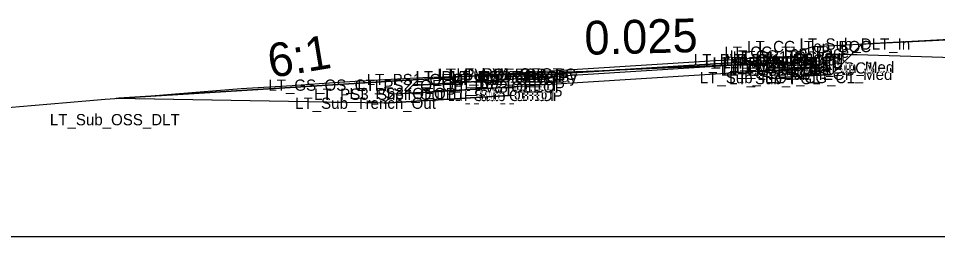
# Model space of a CAD drawing. Extents: x -26 to 2349090, y -10 to 844481.
# Drawn here: x 1098.25 to 1139.03, y 16500 to 16509.69 of the extents above; entities that cross this region are included whole.
import ezdxf

# ---------------------------------------------------------------- set-up
doc = ezdxf.new("R2010")
doc.units = 0
for name, color, linetype in [('Exist CMT Pavement', 7, 'Continuous'), ('Exist Cross Section Cell', 7, 'Continuous'), ('Exist XS Ground Line', 7, 'Continuous'), ('Prop CMT Conc Surface', 7, 'Continuous'), ('Prop CMT Concrete Structures', 7, 'Continuous'), ('Prop CMT Pvmt Course 1', 7, 'Continuous'), ('Prop CMT Pvmt Course 1 CG', 7, 'Continuous'), ('Prop CMT Pvmt Course 1 Wedge', 7, 'Continuous'), ('Prop CMT Pvmt Course 2', 7, 'Continuous'), ('Prop CMT Pvmt Course 2 Wedge', 7, 'Continuous'), ('Prop CMT Pvmt Course 3', 7, 'Continuous'), ('Prop CMT Pvmt Surface', 7, 'Continuous'), ('Prop CMT Pvmt Surface Shoulder', 7, 'Continuous'), ('Prop CMT Pvmt Wedge Surface 1', 7, 'Continuous'), ('Prop CMT Pvmt Wedge Surface 2', 7, 'Continuous'), ('Prop CMT Pvmt Wedge Surface 3', 7, 'Continuous'), ('Prop CMT Shld Paved Course 1', 7, 'Continuous'), ('Prop CMT Shld Paved Course 2', 7, 'Continuous'), ('Prop CMT Shld Paved Course 3', 7, 'Continuous'), ('Prop CMT Slope Grass', 7, 'Continuous'), ('Prop CMT Subgrade Earthwork', 7, 'Continuous'), ('Prop XS Earthwork Shape', 7, 'Continuous'), ('Prop XS SE Text', 7, 'Continuous'), ('Prop XS Side Slope Text', 7, 'Continuous'), ('Scratch_Level_0', 7, 'Continuous')]:
    doc.layers.add(name, color=color, linetype=linetype)

msp = doc.modelspace()

# ---------------------------------------------------------------- linework, layer by layer
at = {"layer": 'Exist CMT Pavement'}
for p, q in [((1123.445, 16507.348), (1125.262, 16507.421)), ((1125.262, 16507.421), (1126.584, 16507.476)), ((1126.584, 16507.476), (1128.028, 16507.535)), ((1128.028, 16507.535), (1129.369, 16507.592)), ((1129.369, 16507.592), (1130.741, 16507.653)), ((1130.741, 16507.653), (1131.727, 16507.696)), ((1131.727, 16507.696), (1131.998, 16507.707)), ((1120.001, 16507.212), (1120.936, 16507.251)), ((1120.936, 16507.251), (1122.512, 16507.311)), ((1122.512, 16507.311), (1123.445, 16507.348))]:
    msp.add_line(p, q, dxfattribs=at)
at = {"layer": 'Exist Cross Section Cell'}
msp.add_line((1000, 16500), (1150, 16500), dxfattribs=at)
at = {"layer": 'Exist XS Ground Line'}
msp.add_lwpolyline([(1097.616, 16505.719), (1098.297, 16505.776), (1099.695, 16505.897), (1100.391, 16505.956), (1102.104, 16506.098), (1103.184, 16506.184), (1103.964, 16506.244), (1105.946, 16506.403), (1108.13, 16506.572), (1110.399, 16506.717), (1111.589, 16506.793), (1113.412, 16506.914), (1114.231, 16506.962), (1116.192, 16507.059), (1116.644, 16507.08), (1117.544, 16507.113), (1119.022, 16507.17), (1119.735, 16507.201), (1120.936, 16507.251), (1122.512, 16507.311), (1123.445, 16507.348), (1125.262, 16507.421), (1126.584, 16507.476), (1128.028, 16507.535), (1129.369, 16507.592), (1130.741, 16507.653), (1131.727, 16507.696), (1133.404, 16507.772), (1133.787, 16507.81), (1134.22, 16508.123), (1135.459, 16508.084), (1145.443, 16507.772)], dxfattribs=at)
at = {"layer": 'Prop CMT Conc Surface'}
for p, q in [((1132.751, 16508.191), (1133.51, 16508.441)), ((1132, 16507.977), (1132.75, 16508.024)), ((1132.75, 16508.024), (1132.751, 16508.191))]:
    msp.add_line(p, q, dxfattribs=at)
at = {"layer": 'Prop CMT Concrete Structures'}
for p, q in [((1132.751, 16508.191), (1133.51, 16508.441)), ((1133.51, 16508.441), (1133.51, 16507.488)), ((1132, 16507.977), (1132.75, 16508.024)), ((1132, 16507.394), (1132, 16507.977)), ((1132.75, 16508.024), (1132.751, 16508.191)), ((1133.51, 16507.488), (1132, 16507.394))]:
    msp.add_line(p, q, dxfattribs=at)
at = {"layer": 'Prop CMT Pvmt Course 1'}
for p, q in [((1132, 16507.977), (1120, 16507.227)), ((1120, 16507.102), (1132, 16507.852)), ((1132, 16507.727), (1132, 16507.977)), ((1132, 16507.852), (1132, 16507.727)), ((1132, 16507.727), (1132, 16507.727)), ((1120, 16507.227), (1120, 16506.977)), ((1120, 16506.977), (1120, 16507.102)), ((1120, 16506.977), (1120, 16506.977))]:
    msp.add_line(p, q, dxfattribs=at)
at = {"layer": 'Prop CMT Pvmt Course 1 CG'}
for p, q in [((1132, 16507.394), (1134.01, 16507.52)), ((1134.01, 16507.52), (1134.324, 16507.206)), ((1132, 16507.061), (1132, 16507.394)), ((1134.324, 16507.206), (1132, 16507.061))]:
    msp.add_line(p, q, dxfattribs=at)
at = {"layer": 'Prop CMT Pvmt Course 1 Wedge'}
for p, q in [((1130.741, 16507.774), (1131.727, 16507.835)), ((1131.727, 16507.835), (1132, 16507.852)), ((1132, 16507.852), (1132, 16507.727)), ((1124.79, 16507.402), (1125.262, 16507.431)), ((1125.262, 16507.421), (1124.79, 16507.402)), ((1125.262, 16507.431), (1126.584, 16507.514)), ((1126.584, 16507.476), (1125.262, 16507.421)), ((1126.584, 16507.514), (1128.028, 16507.604)), ((1128.028, 16507.535), (1126.584, 16507.476)), ((1128.028, 16507.604), (1129.369, 16507.688)), ((1129.369, 16507.592), (1128.028, 16507.535)), ((1129.369, 16507.688), (1130.741, 16507.774)), ((1130.741, 16507.653), (1129.369, 16507.592)), ((1130.964, 16507.663), (1130.741, 16507.653)), ((1131.727, 16507.71), (1130.964, 16507.663)), ((1132, 16507.727), (1131.727, 16507.71))]:
    msp.add_line(p, q, dxfattribs=at)
at = {"layer": 'Prop CMT Pvmt Course 2'}
for p, q in [((1120, 16506.644), (1120, 16506.977)), ((1120, 16506.977), (1120, 16506.977)), ((1120, 16506.977), (1120, 16506.644)), ((1120, 16506.644), (1120, 16506.644))]:
    msp.add_line(p, q, dxfattribs=at)
at = {"layer": 'Prop CMT Pvmt Course 2 Wedge'}
for p, q in [((1130.964, 16507.663), (1131.727, 16507.71)), ((1131.727, 16507.696), (1130.964, 16507.663)), ((1131.727, 16507.71), (1132, 16507.727)), ((1132, 16507.707), (1131.727, 16507.696)), ((1132, 16507.727), (1132, 16507.707))]:
    msp.add_line(p, q, dxfattribs=at)
at = {"layer": 'Prop CMT Pvmt Course 3'}
for p, q in [((1120, 16506.644), (1120, 16506.644)), ((1120, 16506.644), (1120, 16506.269)), ((1120, 16506.269), (1120, 16506.644)), ((1120, 16506.269), (1120, 16506.269))]:
    msp.add_line(p, q, dxfattribs=at)
at = {"layer": 'Prop CMT Pvmt Surface'}
msp.add_line((1132, 16507.977), (1120, 16507.227), dxfattribs=at)
at = {"layer": 'Prop CMT Pvmt Surface Shoulder'}
msp.add_line((1120, 16507.227), (1116, 16506.977), dxfattribs=at)
at = {"layer": 'Prop CMT Pvmt Wedge Surface 1'}
for p, q in [((1132, 16507.852), (1120, 16507.102)), ((1132, 16507.977), (1132, 16507.852)), ((1132, 16507.852), (1132, 16507.852)), ((1120, 16507.102), (1120, 16507.227)), ((1120, 16507.102), (1120, 16507.102))]:
    msp.add_line(p, q, dxfattribs=at)
at = {"layer": 'Prop CMT Pvmt Wedge Surface 2'}
for p, q in [((1132, 16507.977), (1132, 16507.727)), ((1132, 16507.727), (1120, 16506.977)), ((1120, 16506.977), (1120, 16507.227))]:
    msp.add_line(p, q, dxfattribs=at)
at = {"layer": 'Prop CMT Pvmt Wedge Surface 3'}
for p, q in [((1132, 16507.977), (1132, 16507.394)), ((1132, 16507.394), (1120, 16506.644)), ((1120, 16506.644), (1120, 16507.227))]:
    msp.add_line(p, q, dxfattribs=at)
at = {"layer": 'Prop CMT Shld Paved Course 1'}
for p, q in [((1120, 16507.227), (1116, 16506.977)), ((1120, 16506.977), (1120, 16507.227)), ((1116, 16506.977), (1115.733, 16506.711)), ((1115.733, 16506.711), (1120, 16506.977))]:
    msp.add_line(p, q, dxfattribs=at)
at = {"layer": 'Prop CMT Shld Paved Course 2'}
for p, q in [((1115.733, 16506.711), (1115.378, 16506.355)), ((1115.378, 16506.355), (1120, 16506.644)), ((1120, 16506.977), (1115.733, 16506.711)), ((1120, 16506.644), (1120, 16506.977))]:
    msp.add_line(p, q, dxfattribs=at)
at = {"layer": 'Prop CMT Shld Paved Course 3'}
for p, q in [((1120, 16506.644), (1115.378, 16506.355)), ((1120, 16506.269), (1120, 16506.644)), ((1114.878, 16506.324), (1114.478, 16505.924)), ((1114.478, 16505.924), (1120, 16506.269)), ((1115.378, 16506.355), (1114.878, 16506.324))]:
    msp.add_line(p, q, dxfattribs=at)
at = {"layer": 'Prop CMT Slope Grass'}
for p, q in [((1133.51, 16508.441), (1144, 16508.983)), ((1116, 16506.977), (1102.585, 16506.139))]:
    msp.add_line(p, q, dxfattribs=at)
at = {"layer": 'Prop CMT Subgrade Earthwork'}
for p, q in [((1135.67, 16508.553), (1134.324, 16507.206)), ((1132, 16507.394), (1132, 16507.977)), ((1120, 16506.269), (1120.001, 16507.212)), ((1132, 16507.394), (1132, 16507.061)), ((1132, 16507.061), (1134.324, 16507.206)), ((1120, 16506.269), (1114.478, 16505.924)), ((1120, 16506.269), (1120, 16506.269)), ((1114.478, 16505.924), (1102.585, 16506.139))]:
    msp.add_line(p, q, dxfattribs=at)
at = {"layer": 'Prop XS Earthwork Shape'}
for points in [[(1146.316, 16507.489), (1147.334, 16507.506), (1149.183, 16507.543), (1150.096, 16507.57), (1153.053, 16507.671), (1153.383, 16507.678), (1152.243, 16508.818), (1144, 16508.983), (1135.67, 16508.553), (1135.209, 16508.092), (1135.459, 16508.084), (1145.443, 16507.772), (1145.852, 16507.511)], [(1132, 16507.394), (1132, 16507.707), (1133.404, 16507.772), (1133.787, 16507.81), (1134.22, 16508.123), (1135.209, 16508.092), (1134.324, 16507.206), (1132, 16507.061)], [(1119.735, 16507.201), (1120.001, 16507.212), (1120, 16506.269), (1114.478, 16505.924), (1102.607, 16506.139), (1102.714, 16506.147), (1116, 16506.977), (1119.222, 16507.179)], [(1119.222, 16507.179), (1116, 16506.977), (1102.714, 16506.147), (1103.184, 16506.184), (1103.964, 16506.244), (1105.946, 16506.403), (1108.13, 16506.572), (1110.399, 16506.717), (1111.589, 16506.793), (1113.412, 16506.914), (1114.231, 16506.962), (1116.192, 16507.059), (1116.644, 16507.08), (1117.544, 16507.113), (1119.022, 16507.17)]]:
    msp.add_lwpolyline(points, close=True, dxfattribs=at)

# ---------------------------------------------------------------- texts
at = {"layer": 'Prop XS SE Text'}
msp.add_text('0.025', height=1.5, rotation=1.4321, dxfattribs=at).set_placement((1123.38, 16508.071))
at = {"layer": 'Prop XS Side Slope Text'}
msp.add_text('6:1', height=1.5, rotation=9.4623, dxfattribs=at).set_placement((1109.448, 16507.042))
at = {"layer": 'Scratch_Level_0'}
for s, p in [('LT_CG_Top_BOC', (1130.581, 16508.191)), ('LT_Sub_DLT_In', (1132.906, 16508.303)), ('LT_CG_Top_Face', (1129.566, 16507.941)), ('LT_CG_Top_Gut', (1129.809, 16507.774)), ('LT_PV1_PGL', (1129.945, 16507.727)), ('LT_PV1_Overlay_Null', (1128.216, 16507.602)), ('LT_PV_IEEOP_EG', (1129.046, 16507.457)), ('LT_PV2_IEEOP', (1129.488, 16507.477)), ('LT_PV1_IEEOP', (1129.63, 16507.602)), ('LT_PV2_PGL', (1129.803, 16507.477)), ('LT_Sub Tie Out', (1116.836, 16506.962)), ('LT_PV_OEEOP_EG', (1116.887, 16506.962)), ('LT_PV1_OEOT', (1117.685, 16506.977)), ('LT_CG_Bot_IE1', (1129.405, 16507.144)), ('LT_PV3_IEEOP', (1129.488, 16507.144)), ('LT_PV3_PGL', (1129.803, 16507.144)), ('LT_CG1_Shelf_In_Med', (1130.081, 16507.27)), ('LT_CG_Bot_BOC1', (1130.506, 16507.238)), ('LT_Sub_IEOP_Med', (1131.04, 16506.956)), ('LT_PS1_OEOP', (1113.701, 16506.727)), ('LT_PV1_OEOT Overlay', (1115.87, 16506.852)), ('LT_PV2_OEEOP', (1117.327, 16506.727)), ('LT_PV1_OEEOP', (1117.468, 16506.852)), ('LT_PV2_OEOT', (1117.543, 16506.727)), ('LT_Sub_IEOT_CG_C1', (1128.48, 16506.811)), ('LT_Sub_PGL', (1129.779, 16506.769)), ('LT_GS_OS_CTL', (1109.342, 16506.477)), ('LT_PS3_Shelf_Out', (1111.374, 16506.074)), ('LT_PS3_OEOP', (1112.937, 16506.105)), ('LT_PS2_OEOP', (1113.292, 16506.461)), ('LT_PV3_OEEOP', (1117.327, 16506.394)), ('LT_PV3_OEOT', (1117.543, 16506.394)), ('LT_Sub_Trench_Out', (1110.529, 16505.674)), ('LT_Sub_OEEOP', (1117.303, 16506.019)), ('LT_Sub_OEOT', (1117.52, 16506.019)), ('LT_Sub_OSS_DLT', (1099.65, 16504.944))]:
    msp.add_text(s, height=0.5, dxfattribs=at).set_placement(p)

doc.saveas('drawing.dxf')
